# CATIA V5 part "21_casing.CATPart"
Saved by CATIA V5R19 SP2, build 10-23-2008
Part number: 21_casing
Bounding box of the stored display mesh (mm): x -84.98 to 84.98, y -64.5 to 10.5, z -84.98 to 84.98
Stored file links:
  C:\Documents and Settings\anizard\Bureau\13\21_casing.CATPart
  D:\Documents\T\2011-2012\CFAO\ThinkMotion\1\Support.CATPart
  C:\Program Files (x86)\Dassault Systemes\B19\intel_a\reffiles\standard\MetricThickPitch.txt
  C:\Documents and Settings\anizard\Bureau\13\anizard.CATProduct
  D:\Documents\T\2011-2012\CFAO\ThinkMotion\2\Squelette.CATPart
  Squelette.CATPart
  D:\Documents\T\2011-2012\CFAO\ThinkMotion\6\Squelette_fixe.CATPart
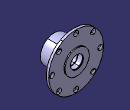
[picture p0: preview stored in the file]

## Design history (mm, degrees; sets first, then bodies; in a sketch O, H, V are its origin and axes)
External parameters (linked from other documents)
  External.nb_trou_21_32 = 8
  External.module = 2 mm
  External.Z1 = 51
Set1
  Line1: linked copy from another document
  Point1: linked copy from another document
  Plane1 to Plane5: linked copy from another document
  Point2 to Point4: linked copy from another document
Body1 (main body)
  Sketch1 on yz-plane, origin (0, 0, 0), H (0, 1, 0), V (0, 0, 1)
    line L1 (-61.5, 23.75) -> (-64.5, 23.75)
    line L2 (7.5, 37.5) -> (10.5, 37.5)
    line L3 (-14, 42.5) -> (-60.5, 42.5)
    arc A1 centre (-60.5, 41.5) radius 1 from (-60.5, 42.5) to (-61.5, 41.5) ccw
    line L4 (-61.5, 41.5) -> (-61.5, 23.75)
    line L5 (-64.5, 20) -> (-37, 20)
    line L6 (-7, 20) -> (6.9, 20)
    line L7 (8.75, 20) -> (10.5, 20)
    line L8 (6.9, 21.25) -> (8.75, 21.25)
    line L9 (8.75, 21.25) -> (8.75, 20)
    line L10 (-7, 17.5) -> (-7, 20)
    line L11 (-37, 17.5) -> (-7, 17.5)
    line L12 (7.5, 85) -> (0, 85)
    line L13 (-64.5, 23.75) -> (-64.5, 20)
    line L14 (-37, 20) -> (-37, 17.5)
    line L15 (7.5, 37.5) -> (7.5, 85)
    line L16 (10.5, 20) -> (10.5, 37.5)
    line L17 (6.9, 20) -> (6.9, 21.25)
    line L18 (0, 85) -> (0, 59)
    line L19 (0, 59) -> (-4, 59)
    line L20 (-4, 59) -> (-4, 52.5)
    arc A2 centre (-14, 52.5) radius 10 from (-4, 52.5) to (-14, 42.5) cw
    construction line L21 (-136.6578, 0) -> (140.5449, 0)
    reference projected line E1 (0, 0) -> (120, 0) from Line1
    reference projected point E2 (0, 0) from Point1
    reference intersected line E3 through (-37, 0) direction (0, 1) from Plane1
    reference intersected line E4 through (-7, 0) direction (0, 1) from Plane2
    reference intersected line E5 through (8.75, 0) direction (0, 1) from Plane3
    reference intersected line E6 through (7.5, 0) direction (0, 1) from Plane4
    reference intersected line E7 through (10.5, 0) direction (0, 1) from Plane5
    reference intersected line E8 through (-37, 0) direction (0, 1) from Plane1
    reference projected point E9 (0, 20) from Point3
    reference projected point E10 (0, 37.5) from Point4
    radius A1 = 1
    length L8 = 1.85
    radius A2 = 10
    distance L13 L4 = 3
    distance L20 L18 = 4
    distance L19 L21 = 59
    distance L3 L21 = 42.5
    distance L1 L21 = 23.75
    distance L11 L21 = 17.5
    distance L8 L21 = 21.25
    distance L12 L21 = 85 {= External.module *External.Z1 /2 +34mm}
    distance L13 E8 = 27.5
    tangency: A1 L3, A1 L4, A2 L20, A2 L3
    coincidence: L7 L5, L21 E1, L18 E2, L14 E3, L10 E4, L9 E5, L15 E6, L16 E7, L6 L5, L6 E9, L2 E10
    horizontal: L11 H, L6 H, L5 H, L1 H, L3 H, L19 H, L12 H, L2 H, L8 H, L7 H, L21 H
    vertical: L9 V, L17 V, L10 V, L14 V, L13 V, L4 V, L18 V, L15 V, L16 V, L20 V
  Shaft1: profile Sketch1, axis Line1, angle 360
  Sketch2 on face of Shaft1 from Sketch1.L15, origin (0, 7.5, 75), H (1, 0, 0), V (0, 0, -1)
    point P1 (0, 0)
    construction line L1 (-59.3985, -10) -> (70.5115, -10)
    reference projected circle E1 centre (0, 75) radius 85 from edge [face of Shaft1 from Sketch1.L12 | face of Shaft1 from Sketch1.L15]
    axis line L2 (0, -49.344) -> (0, 87.4572)
    reference projected point E2 (0, 75) from Point1
    distance P1 L1 = 10
    horizontal: L1 H
    tangency: L1 E1
    vertical: L2 V
    coincidence: L2 E2, P1 L2
  Hole1: placed by Sketch2, at (0, 7.5, 75) direction (0, -1, 0), diameter 7.5, through (limit type 6), countersink depth 4, countersink angle 90
  CircPattern1: of Hole1, instances 9, angular step 45, axis from Line1
  Sketch3 on face of Shaft1 from Sketch1.L16, origin (0, 10.5, 34), H (1, 0, 0), V (0, 0, -1)
    point P1 (0, 0)
    reference projected point E1 (0, 0) from Point2
    coincidence: P1 E1
  Hole2: placed by Sketch3, at (0, 10.5, 34) direction (0, -1, 0), diameter 4.134, depth 13, V-bottom angle 120, threaded "M5", thread diameter 5, thread depth 10, pitch 0.8
  CircPattern2: of Hole2, instances 9 {= External.nb_trou_21_32  + 1}, angular step 45, axis from Line1
Current feature: CircPattern1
